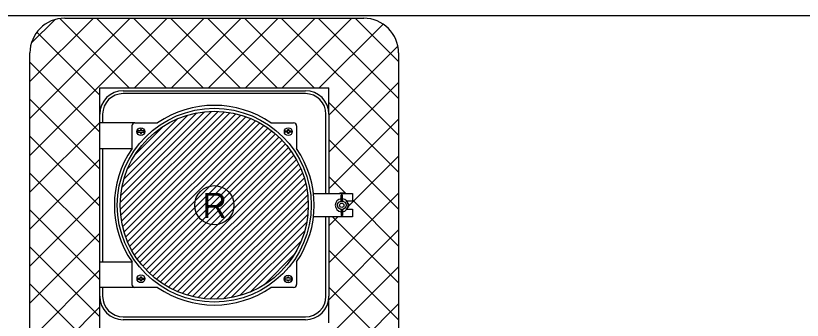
# Model space of a CAD drawing. Extents: x 99862 to 103680, y 99470 to 105076.
# Drawn here: x 101299.3 to 101751, y 104900.5 to 105075.5 of the extents above; entities that cross this region are included whole.
import ezdxf

# ---------------------------------------------------------------- set-up
doc = ezdxf.new("R2010")
doc.units = 0
for name, color, linetype in [('Level 1', 7, 'Continuous'), ('Level 12', 7, 'Continuous'), ('Level 18', 7, 'Continuous'), ('Level 20', 7, 'Continuous'), ('Level 26', 7, 'Continuous'), ('Level 4', 7, 'Continuous')]:
    doc.layers.add(name, color=color, linetype=linetype)

msp = doc.modelspace()

# ---------------------------------------------------------------- linework, layer by layer
at = {"layer": 'Level 1'}
for p, q in [((101307.44, 104995.25), (101386.3, 105074.1)), ((101307.44, 105016.46), (101365.09, 105074.1)), ((101307.44, 105037.67), (101343.87, 105074.1)), ((101364.51, 105034.1), (101324.7, 105073.91)), ((101327.44, 105074.1), (101499.12, 105074.1)), ((101385.72, 105034.1), (101345.72, 105074.1)), ((101406.94, 105034.1), (101366.94, 105074.1)), ((101367.51, 105034.1), (101407.51, 105074.1)), ((101428.15, 105034.1), (101388.15, 105074.1)), ((101388.73, 105034.1), (101428.73, 105074.1)), ((101449.36, 105034.1), (101409.36, 105074.1)), ((101409.94, 105034.1), (101449.94, 105074.1)), ((101470.58, 105034.1), (101430.58, 105074.1)), ((101431.15, 105034.1), (101471.15, 105074.1)), ((101519.12, 105006.77), (101451.79, 105074.1)), ((101452.37, 105034.1), (101492.37, 105074.1)), ((101519.12, 105027.99), (101473, 105074.1)), ((101519.12, 105049.2), (101494.22, 105074.1)), ((101308.24, 105059.68), (101321.87, 105073.31)), ((101473.58, 105034.1), (101510.22, 105070.74)), ((101347.44, 105029.95), (101311.38, 105066.02)), ((101479.07, 105018.38), (101518.73, 105058.04)), ((101307.44, 104609.1), (101307.44, 105054.1)), ((101519.12, 105054.1), (101519.12, 104609.1)), ((101347.44, 105008.74), (101307.44, 105048.74)), ((101347.44, 105034.1), (101479.07, 105034.1)), ((101347.44, 105034.1), (101347.44, 104629.1)), ((101479.07, 104997.16), (101519.12, 105037.21)), ((101479.07, 105020.06), (101479.07, 105034.1)), ((101360.99, 105032.41), (101465.62, 105032.41)), ((101465.62, 105030.73), (101360.99, 105030.73)), ((101347.44, 104987.53), (101307.44, 105027.53)), ((101519.12, 104985.56), (101479.07, 105025.61)), ((101349.18, 105018.91), (101349.18, 105013.85)), ((101477.43, 104973.35), (101477.43, 105018.91)), ((101479.07, 104975.95), (101519.12, 105016)), ((101479.12, 105018.91), (101479.12, 104973.35)), ((101307.44, 104974.03), (101347.44, 105014.03)), ((101367.74, 105013.85), (101347.44, 105013.85)), ((101366.06, 104999.15), (101366.06, 105012.16)), ((101367.74, 105013.85), (101380.76, 105013.85)), ((101445.85, 105013.85), (101458.87, 105013.85)), ((101460.56, 105012.16), (101460.56, 104999.15)), ((101347.44, 104966.31), (101307.44, 105006.31)), ((101519.12, 104964.35), (101479.07, 105004.39)), ((101347.44, 104999.15), (101366.06, 104999.15)), ((101349.18, 104999.15), (101349.18, 104934.05)), ((101307.44, 104952.82), (101347.44, 104992.82)), ((101490.79, 104966.46), (101519.12, 104994.79)), ((101347.44, 104945.1), (101307.44, 104985.1)), ((101488.9, 104973.35), (101479.07, 104983.18)), ((101307.44, 104931.61), (101347.44, 104971.61)), ((101470.28, 104973.35), (101478.24, 104973.35)), ((101478.31, 104973.35), (101492.62, 104973.35)), ((101479.07, 104933.52), (101519.12, 104973.57)), ((101479.12, 104973.4), (101479.24, 104973.4)), ((101479.24, 104973.35), (101479.24, 104973.4)), ((101479.24, 104973.4), (101479.4, 104973.4)), ((101479.4, 104973.35), (101479.4, 104973.4)), ((101480.88, 104973.35), (101480.88, 104973.4)), ((101492.6, 104973.35), (101492.6, 104973.4)), ((101492.62, 104973.35), (101492.62, 104968.85)), ((101492.62, 104968.85), (101489.48, 104968.85)), ((101519.12, 104943.13), (101492.62, 104969.63)), ((101347.44, 104923.89), (101307.44, 104963.89)), ((101489.57, 104964.4), (101492.62, 104964.4)), ((101492.62, 104964.4), (101492.62, 104959.85)), ((101478.24, 104959.85), (101470.28, 104959.85)), ((101477.43, 104914.29), (101477.43, 104959.85)), ((101492.62, 104959.85), (101478.31, 104959.85)), ((101479.07, 104954.74), (101484.18, 104959.85)), ((101479.12, 104959.85), (101479.12, 104914.29)), ((101519.12, 104921.92), (101481.19, 104959.85)), ((101479.07, 104912.31), (101519.12, 104952.36)), ((101307.44, 104910.39), (101347.44, 104950.39)), ((101347.44, 104902.67), (101307.44, 104942.67)), ((101519.12, 104900.71), (101479.07, 104940.75)), ((101347.44, 104934.05), (101366.06, 104934.05)), ((101366.06, 104921.04), (101366.06, 104934.05)), ((101460.56, 104934.05), (101460.56, 104921.04)), ((101479.07, 104891.1), (101519.12, 104931.15)), ((101307.44, 104889.18), (101347.44, 104929.18)), ((101347.44, 104881.46), (101307.44, 104921.46)), ((101367.74, 104919.35), (101347.44, 104919.35)), ((101349.18, 104919.35), (101349.18, 104914.29)), ((101380.76, 104919.35), (101367.74, 104919.35)), ((101458.87, 104919.35), (101445.85, 104919.35)), ((101519.12, 104879.49), (101479.07, 104919.54)), ((101479.07, 104899.1), (101479.07, 104913.14)), ((101307.44, 104867.97), (101347.44, 104907.97)), ((101479.07, 104869.88), (101519.12, 104909.93)), ((101360.99, 104902.48), (101465.62, 104902.48)), ((101465.62, 104900.79), (101360.99, 104900.79))]:
    msp.add_line(p, q, dxfattribs=at)
for radius in [55.69, 54]:
    msp.add_circle((101413.31, 104966.6), radius, dxfattribs=at)
for centre, radius, start, end in [((101327.44, 105054.1), 20, 90, 180), ((101499.12, 105054.1), 20, 0, 90), ((101360.99, 105018.91), 13.5, 90, 180), ((101360.99, 105018.91), 11.81, 90, 180), ((101465.62, 105018.91), 13.5, 0, 90), ((101465.62, 105018.91), 11.81, 0, 90), ((101413.31, 104966.6), 57.38, 55.4397, 124.5603), ((101367.74, 105012.16), 1.69, 90, 180), ((101458.87, 105012.16), 1.69, 0, 90), ((101413.31, 104966.6), 57.38, 145.4397, 214.5603), ((101413.31, 104966.6), 57.38, 325.4397, 34.5603), ((101367.74, 104921.04), 1.69, 180, 270), ((101458.87, 104921.04), 1.69, 270, 0), ((101413.31, 104966.6), 57.38, 235.4397, 304.5603), ((101360.99, 104914.29), 13.5, 180, 270), ((101360.99, 104914.29), 11.81, 180, 270), ((101465.62, 104914.29), 13.5, 270, 0), ((101465.62, 104914.29), 11.81, 270, 0)]:
    msp.add_arc(centre, radius, start, end, dxfattribs=at)
at = {"layer": 'Level 12'}
for p, q in [((101359.35, 104968.17), (101411.73, 105020.55)), ((101359.38, 104964.38), (101415.55, 105020.55)), ((101359.62, 104972.26), (101407.64, 105020.28)), ((101359.64, 104960.83), (101419.1, 105020.29)), ((101360.11, 104957.47), (101422.45, 105019.82)), ((101360.28, 104976.74), (101403.19, 105019.64)), ((101360.75, 104954.3), (101425.63, 105019.17)), ((101361.51, 104981.78), (101398.12, 105018.39)), ((101361.55, 104951.28), (101428.64, 105018.37)), ((101362.49, 104948.4), (101431.51, 105017.42)), ((101363.55, 104945.64), (101434.25, 105016.35)), ((101363.64, 104987.74), (101392.17, 105016.27)), ((101364.74, 104943.01), (101436.88, 105015.15)), ((101366.05, 104940.5), (101439.4, 105013.85)), ((101367.47, 104938.1), (101441.81, 105012.45)), ((101367.93, 104995.84), (101384.12, 105012.03)), ((101368.98, 104935.8), (101444.12, 105010.94)), ((101370.59, 104933.59), (101446.31, 105009.31)), ((101372.3, 104931.48), (101448.41, 105007.6)), ((101374.11, 104929.48), (101450.43, 105005.79)), ((101376.03, 104927.57), (101452.35, 105003.89)), ((101378.03, 104925.75), (101454.17, 105001.89)), ((101380.12, 104924.03), (101455.88, 104999.79)), ((101382.3, 104922.39), (101457.5, 104997.59)), ((101384.61, 104920.88), (101459.02, 104995.3)), ((101387.01, 104919.46), (101460.45, 104992.91)), ((101389.52, 104918.15), (101461.77, 104990.4)), ((101392.13, 104916.95), (101462.96, 104987.78)), ((101394.87, 104915.86), (101464.04, 104985.03)), ((101397.72, 104914.9), (101464.99, 104982.17)), ((101400.73, 104914.09), (101465.8, 104979.16)), ((101403.9, 104913.44), (101466.46, 104976)), ((101407.23, 104912.95), (101466.94, 104972.66)), ((101410.76, 104912.67), (101467.22, 104969.13)), ((101414.55, 104912.64), (101467.26, 104965.35)), ((101418.62, 104912.89), (101467.02, 104961.29)), ((101423.05, 104913.5), (101466.42, 104956.87)), ((101428.05, 104914.68), (101465.23, 104951.86)), ((101433.88, 104916.69), (101463.2, 104946.01)), ((101441.69, 104920.69), (101459.25, 104938.25))]:
    msp.add_line(p, q, dxfattribs=at)
at = {"layer": 'Level 18'}
msp.add_circle((101413.31, 104966.6), 11.25, dxfattribs=at)
at = {"layer": 'Level 26'}
msp.add_lwpolyline([(99862, 102999.5), (103151, 102999.5), (103151, 105075.5), (99862, 105075.5)], close=True, dxfattribs=at)
at = {"layer": 'Level 4'}
for p, q in [((101485.42, 104973.63), (101487.64, 104973.63)), ((101485.42, 104973.63), (101485.42, 104973.4)), ((101486.15, 104970.54), (101486.15, 104972.38)), ((101486.91, 104972.38), (101486.15, 104972.38)), ((101486.15, 104969.73), (101486.15, 104970.54)), ((101486.91, 104970.54), (101486.91, 104972.38)), ((101486.91, 104969.73), (101486.91, 104970.54)), ((101487.64, 104973.63), (101487.64, 104973.63)), ((101487.64, 104973.4), (101487.64, 104973.63)), ((101486.15, 104969.14), (101486.15, 104969.73)), ((101486.91, 104969.14), (101486.91, 104969.73)), ((101486.15, 104964), (101486.15, 104963.4)), ((101486.15, 104963.4), (101486.15, 104962.59)), ((101486.15, 104962.59), (101486.15, 104960.75)), ((101486.91, 104964), (101486.91, 104963.4)), ((101486.91, 104963.4), (101486.91, 104962.59)), ((101486.91, 104962.59), (101486.91, 104960.75)), ((101486.91, 104960.75), (101486.15, 104960.75))]:
    msp.add_line(p, q, dxfattribs=at)
for centre, radius in [((101371.13, 105008.9), 2.25), ((101455.78, 105008.9), 2.25), ((101486.53, 104966.57), 2.45), ((101486.53, 104966.55), 1.25), ((101371.18, 104924.35), 2.25), ((101455.73, 104924.21), 2.25)]:
    msp.add_circle(centre, radius, dxfattribs=at)
for centre, radius, start, end in [((101371.13, 105008.9), 1.91, 167.4639, 192.4931), ((101371.13, 105008.9), 1.91, 347.5069, 12.5361), ((101455.78, 105008.9), 1.91, 167.4639, 192.4931), ((101455.78, 105008.9), 1.91, 347.5069, 12.5361), ((101486.53, 104966.57), 3.73, 95.8352, 264.1648), ((101486.53, 104966.57), 3.73, 275.8352, 84.1648), ((101486.53, 104966.57), 2.89, 97.5642, 97.5998), ((101486.53, 104966.57), 2.89, 82.4002, 82.4567), ((101489.54, 104966.55), 1.25, 295.8954, 63.3748), ((101486.53, 104966.57), 2.89, 262.4002, 262.4483), ((101486.53, 104966.57), 2.89, 277.5551, 277.5998), ((101371.18, 104924.35), 1.91, 167.5069, 192.5361), ((101371.18, 104924.35), 1.91, 347.4639, 12.4931), ((101455.73, 104924.21), 1.91, 167.5069, 192.5361), ((101455.73, 104924.21), 1.91, 347.4639, 12.4931)]:
    msp.add_arc(centre, radius, start, end, dxfattribs=at)
for points, degree in [([(101370.84, 105009.31), (101370.8, 105009.31), (101370.76, 105009.31), (101370.71, 105009.31), (101370.44, 105009.31), (101370.16, 105009.31), (101369.9, 105009.31), (101369.67, 105009.31), (101369.45, 105009.31), (101369.27, 105009.31)], 3), ([(101369.27, 105008.49), (101369.41, 105008.49), (101369.57, 105008.49), (101369.75, 105008.49), (101369.97, 105008.49), (101370.21, 105008.49), (101370.46, 105008.49), (101370.58, 105008.49), (101370.71, 105008.49), (101370.84, 105008.49)], 3), ([(101371.44, 105010.02), (101371.34, 105010.02), (101371.24, 105010.02), (101371.14, 105010.02), (101371.04, 105010.02), (101370.94, 105010.02), (101370.84, 105010.02)], 3), ([(101370.84, 105010.02), (101370.84, 105009.92), (101370.84, 105009.81), (101370.84, 105009.69), (101370.84, 105009.57), (101370.84, 105009.44), (101370.84, 105009.31)], 3), ([(101370.84, 105008.49), (101370.84, 105008.24), (101370.84, 105008), (101370.84, 105007.77)], 2), ([(101370.84, 105007.77), (101370.94, 105007.77), (101371.04, 105007.77), (101371.14, 105007.77), (101371.24, 105007.77), (101371.34, 105007.77), (101371.44, 105007.77)], 3), ([(101371.44, 105009.31), (101371.44, 105009.55), (101371.44, 105009.8), (101371.44, 105010.02)], 2), ([(101372.99, 105009.31), (101372.85, 105009.31), (101372.68, 105009.31), (101372.5, 105009.31), (101372.28, 105009.31), (101372.04, 105009.31), (101371.8, 105009.31), (101371.68, 105009.31), (101371.56, 105009.31), (101371.44, 105009.31)], 3), ([(101371.44, 105008.49), (101371.47, 105008.49), (101371.51, 105008.49), (101371.54, 105008.49), (101371.82, 105008.49), (101372.1, 105008.49), (101372.35, 105008.49), (101372.59, 105008.49), (101372.81, 105008.49), (101372.99, 105008.49)], 3), ([(101371.44, 105007.77), (101371.44, 105007.88), (101371.44, 105007.99), (101371.44, 105008.1), (101371.44, 105008.23), (101371.44, 105008.36), (101371.44, 105008.49)], 3), ([(101453.91, 105009.31), (101454.06, 105009.31), (101454.23, 105009.31), (101454.4, 105009.31), (101454.62, 105009.31), (101454.86, 105009.31), (101455.11, 105009.31), (101455.23, 105009.31), (101455.35, 105009.31), (101455.47, 105009.31)], 3), ([(101455.47, 105008.49), (101455.43, 105008.49), (101455.4, 105008.49), (101455.36, 105008.49), (101455.09, 105008.49), (101454.81, 105008.49), (101454.55, 105008.49), (101454.32, 105008.49), (101454.1, 105008.49), (101453.91, 105008.49)], 3), ([(101455.47, 105009.31), (101455.47, 105009.55), (101455.47, 105009.8), (101455.47, 105010.02)], 2), ([(101455.47, 105010.02), (101455.57, 105010.02), (101455.67, 105010.02), (101455.77, 105010.02), (101455.87, 105010.02), (101455.97, 105010.02), (101456.07, 105010.02)], 3), ([(101455.47, 105007.77), (101455.47, 105007.88), (101455.47, 105007.99), (101455.47, 105008.1), (101455.47, 105008.23), (101455.47, 105008.36), (101455.47, 105008.49)], 3), ([(101456.07, 105007.77), (101455.97, 105007.77), (101455.87, 105007.77), (101455.77, 105007.77), (101455.67, 105007.77), (101455.57, 105007.77), (101455.47, 105007.77)], 3), ([(101456.07, 105010.02), (101456.07, 105009.92), (101456.07, 105009.81), (101456.07, 105009.69), (101456.07, 105009.57), (101456.07, 105009.44), (101456.07, 105009.31)], 3), ([(101456.07, 105009.31), (101456.11, 105009.31), (101456.15, 105009.31), (101456.19, 105009.31), (101456.47, 105009.31), (101456.75, 105009.31), (101457, 105009.31), (101457.24, 105009.31), (101457.46, 105009.31), (101457.64, 105009.31)], 3), ([(101457.64, 105008.49), (101457.5, 105008.49), (101457.33, 105008.49), (101457.15, 105008.49), (101456.94, 105008.49), (101456.69, 105008.49), (101456.45, 105008.49), (101456.32, 105008.49), (101456.2, 105008.49), (101456.07, 105008.49)], 3), ([(101456.07, 105008.49), (101456.07, 105008.24), (101456.07, 105008), (101456.07, 105007.77)], 2), ([(101486.15, 104969.1), (101486.15, 104969.14), (101486.15, 104969.19), (101486.15, 104969.23), (101486.15, 104969.26), (101486.15, 104969.3), (101486.15, 104969.33), (101486.15, 104969.36), (101486.15, 104969.38), (101486.15, 104969.4), (101486.15, 104969.42), (101486.15, 104969.43), (101486.15, 104969.43), (101486.15, 104969.43), (101486.15, 104969.43), (101486.15, 104969.42), (101486.15, 104969.42), (101486.15, 104969.41), (101486.15, 104969.41)], 3), ([(101486.15, 104969.14), (101486.15, 104969.23), (101486.15, 104969.32), (101486.15, 104969.41)], 2), ([(101486.91, 104969.41), (101486.91, 104969.43), (101486.91, 104969.43), (101486.91, 104969.43), (101486.91, 104969.43), (101486.91, 104969.42), (101486.91, 104969.41), (101486.91, 104969.39), (101486.91, 104969.37), (101486.91, 104969.35), (101486.91, 104969.32), (101486.91, 104969.29), (101486.91, 104969.25), (101486.91, 104969.21), (101486.91, 104969.17), (101486.91, 104969.13), (101486.91, 104969.12), (101486.91, 104969.11), (101486.91, 104969.1)], 3), ([(101486.91, 104969.14), (101486.91, 104969.23), (101486.91, 104969.32), (101486.91, 104969.41)], 2), ([(101486.15, 104963.72), (101486.15, 104963.71), (101486.15, 104963.7), (101486.15, 104963.7), (101486.15, 104963.7), (101486.15, 104963.71), (101486.15, 104963.72), (101486.15, 104963.74), (101486.15, 104963.76), (101486.15, 104963.79), (101486.15, 104963.81), (101486.15, 104963.85), (101486.15, 104963.88), (101486.15, 104963.92), (101486.15, 104963.96), (101486.15, 104964), (101486.15, 104964.01), (101486.15, 104964.02), (101486.15, 104964.03)], 3), ([(101486.15, 104964), (101486.15, 104963.9), (101486.15, 104963.81), (101486.15, 104963.72)], 2), ([(101486.91, 104964.03), (101486.91, 104963.99), (101486.91, 104963.95), (101486.91, 104963.91), (101486.91, 104963.87), (101486.91, 104963.83), (101486.91, 104963.8), (101486.91, 104963.77), (101486.91, 104963.75), (101486.91, 104963.73), (101486.91, 104963.72), (101486.91, 104963.71), (101486.91, 104963.7), (101486.91, 104963.7), (101486.91, 104963.7), (101486.91, 104963.71), (101486.91, 104963.72), (101486.91, 104963.72), (101486.91, 104963.72)], 3), ([(101486.91, 104964), (101486.91, 104963.9), (101486.91, 104963.81), (101486.91, 104963.72)], 2), ([(101370.89, 104925.48), (101370.99, 104925.48), (101371.09, 104925.48), (101371.19, 104925.48), (101371.29, 104925.48), (101371.39, 104925.48), (101371.49, 104925.48)], 3), ([(101370.89, 104924.77), (101370.89, 104925.01), (101370.89, 104925.25), (101370.89, 104925.48)], 2), ([(101371.49, 104925.48), (101371.49, 104925.37), (101371.49, 104925.26), (101371.49, 104925.15), (101371.49, 104925.02), (101371.49, 104924.89), (101371.49, 104924.77)], 3), ([(101455.42, 104925.33), (101455.42, 104925.22), (101455.42, 104925.11), (101455.42, 104925), (101455.42, 104924.88), (101455.42, 104924.75), (101455.42, 104924.62)], 3), ([(101456.02, 104925.33), (101455.92, 104925.33), (101455.82, 104925.33), (101455.72, 104925.33), (101455.62, 104925.33), (101455.52, 104925.33), (101455.42, 104925.33)], 3), ([(101456.02, 104924.62), (101456.02, 104924.86), (101456.02, 104925.11), (101456.02, 104925.33)], 2), ([(101369.32, 104924.77), (101369.46, 104924.77), (101369.62, 104924.77), (101369.8, 104924.77), (101370.02, 104924.77), (101370.26, 104924.77), (101370.51, 104924.77), (101370.63, 104924.77), (101370.76, 104924.77), (101370.89, 104924.77)], 3), ([(101370.89, 104923.94), (101370.85, 104923.94), (101370.8, 104923.94), (101370.76, 104923.94), (101370.48, 104923.94), (101370.2, 104923.94), (101369.95, 104923.94), (101369.72, 104923.94), (101369.5, 104923.94), (101369.32, 104923.94)], 3), ([(101370.89, 104923.23), (101370.89, 104923.34), (101370.89, 104923.45), (101370.89, 104923.56), (101370.89, 104923.68), (101370.89, 104923.81), (101370.89, 104923.94)], 3), ([(101371.49, 104923.23), (101371.39, 104923.23), (101371.29, 104923.23), (101371.19, 104923.23), (101371.09, 104923.23), (101370.99, 104923.23), (101370.89, 104923.23)], 3), ([(101371.49, 104924.77), (101371.52, 104924.77), (101371.56, 104924.77), (101371.59, 104924.77), (101371.87, 104924.77), (101372.15, 104924.77), (101372.4, 104924.77), (101372.64, 104924.77), (101372.86, 104924.77), (101373.04, 104924.77)], 3), ([(101373.04, 104923.94), (101372.9, 104923.94), (101372.73, 104923.94), (101372.55, 104923.94), (101372.33, 104923.94), (101372.09, 104923.94), (101371.84, 104923.94), (101371.73, 104923.94), (101371.61, 104923.94), (101371.49, 104923.94)], 3), ([(101371.49, 104923.94), (101371.49, 104923.7), (101371.49, 104923.45), (101371.49, 104923.23)], 2), ([(101455.42, 104924.62), (101455.38, 104924.62), (101455.35, 104924.62), (101455.32, 104924.62), (101455.04, 104924.62), (101454.76, 104924.62), (101454.5, 104924.62), (101454.27, 104924.62), (101454.05, 104924.62), (101453.87, 104924.62)], 3), ([(101453.87, 104923.79), (101454.01, 104923.79), (101454.18, 104923.79), (101454.36, 104923.79), (101454.57, 104923.79), (101454.82, 104923.79), (101455.06, 104923.79), (101455.18, 104923.79), (101455.3, 104923.79), (101455.42, 104923.79)], 3), ([(101455.42, 104923.79), (101455.42, 104923.55), (101455.42, 104923.31), (101455.42, 104923.08)], 2), ([(101455.42, 104923.08), (101455.52, 104923.08), (101455.62, 104923.08), (101455.72, 104923.08), (101455.82, 104923.08), (101455.92, 104923.08), (101456.02, 104923.08)], 3), ([(101457.59, 104924.62), (101457.45, 104924.62), (101457.28, 104924.62), (101457.11, 104924.62), (101456.89, 104924.62), (101456.64, 104924.62), (101456.4, 104924.62), (101456.27, 104924.62), (101456.15, 104924.62), (101456.02, 104924.62)], 3), ([(101456.02, 104923.79), (101456.06, 104923.79), (101456.1, 104923.79), (101456.14, 104923.79), (101456.42, 104923.79), (101456.7, 104923.79), (101456.96, 104923.79), (101457.19, 104923.79), (101457.41, 104923.79), (101457.59, 104923.79)], 3), ([(101456.02, 104923.08), (101456.02, 104923.19), (101456.02, 104923.3), (101456.02, 104923.41), (101456.02, 104923.54), (101456.02, 104923.66), (101456.02, 104923.79)], 3)]:
    msp.add_open_spline(points, degree=degree, dxfattribs=at)

# ---------------------------------------------------------------- texts
at = {"layer": 'Level 20'}
msp.add_text('R', height=14.4, dxfattribs=at).set_placement((101406.54, 104959.28))

doc.saveas('drawing.dxf')
